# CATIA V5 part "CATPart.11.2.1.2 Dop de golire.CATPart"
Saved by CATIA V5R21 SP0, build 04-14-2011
Part number: Buson de aerisire
Bounding box of the stored display mesh (mm): x 0 to 30, y -13.885 to 13.885, z -13.885 to 13.885
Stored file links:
  C:\Users\MIRCEA\Desktop\MOM\Mogan\model\CATPart.11.2.1.2 Dop de golire.CATPart
  C:\Program Files\Dassault Systemes\B21\win_b64\reffiles\standard\MetricThinPitch.txt
  C:\Program Files\Dassault Systemes\B21\win_b64\reffiles\standard\MetricThickPitch.txt
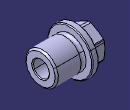
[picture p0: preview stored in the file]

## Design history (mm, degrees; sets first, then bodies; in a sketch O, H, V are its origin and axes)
Parameters
  d = 20 mm
  S = 19 mm
  D = 21.1 mm
  K = 8 mm
  D1 = 28 mm
  b = 18 mm
  l = 30 mm
  d1 = 10 mm
Body1 (main body)
  Sketch1 on xy-plane, origin (0, 0, 0), H (1, 0, 0), V (0, 1, 0)
    line L1 (0, 0) -> (0, 9.5)
    point P1 (0, 9.5)
    line L2 (0, 9.5) -> (0.2813, 10.55)
    line L3 (0.2813, 10.55) -> (8, 10.55)
    line L4 (8, 10.55) -> (8, 14)
    line L5 (8, 14) -> (12, 14)
    line L6 (12, 14) -> (12, 10)
    arc A1 centre (13.5, 10) radius 1.5 from (12, 10) to (15, 10) ccw
    point P8 (15, 10)
    line L7 (15, 10) -> (30, 10)
    line L8 (30, 10) -> (30, 5)
    line L9 (30, 5) -> (8.8868, 5)
    point P12 (6, 0)
    line L10 (6, 0) -> (0, 0)
    line L11 (8.8868, 5) -> (6, 0)
    angle L1 L2 = 15
    distance P1 O = 9.5 {= S/2}
    distance L3 L10 = 10.55 {= D/2}
    distance L9 L10 = 5 {= d1/2}
    distance L10 L5 = 14 {= D1/2}
    distance L7 L10 = 10 {= d/2}
    distance L6 L8 = 18 {= b}
    distance L1 L4 = 8 {= K}
    distance L8 L1 = 30
    distance P12 L8 = 24 {= l-6mm}
    angle L11 L10 = 60
    distance P8 L6 = 3
    distance A1 L10 = 8.5 {= d/2-1.5 mm}
    vertical: L1 V, L4 V, L6 V, L8 V
    horizontal: L3 H, L5 H, L7 H, L9 H, L10 H
    tangency: A1 L6
    coincidence: P12 H
  Shaft1: profile Sketch1, axis Sketch1.H, angle 360
  Sketch2 on face of Shaft1 from Sketch1.L1, origin (0, 0, 0), H (0, -1, 0), V (0, 0, 1)
    point P1 (0.4592, -10.96)
    point P2 (9.7213, -5.0824)
    point P3 (9.2621, 5.8777)
    point P4 (-0.4592, 10.96)
    point P5 (-9.7213, 5.0824)
    point P6 (-9.2621, -5.8777)
    point P7 (5.0902, -8.0212)
    line L1 (0.4592, -10.96) -> (9.7213, -5.0824)
    line L2 (9.7213, -5.0824) -> (9.2621, 5.8777)
    line L3 (9.2621, 5.8777) -> (-0.4592, 10.96)
    line L4 (-0.4592, 10.96) -> (-9.7213, 5.0824)
    line L5 (-9.7213, 5.0824) -> (-9.2621, -5.8777)
    line L6 (-9.2621, -5.8777) -> (0.4592, -10.96)
    construction line L7 (0, 0) -> (5.0902, -8.0212)
    construction circle A1 centre (0, 0) radius 10.9697
    construction arc A2 centre (-9.7213, 5.0824) radius 10.9697 from (-0.4592, 10.96) to (-9.2621, -5.8777) cw
    construction arc A3 centre (9.7213, -5.0824) radius 10.9697 from (9.2621, 5.8777) to (0.4592, -10.96) ccw
    distance L1 L4 = 19 {= S}
    coincidence: A1 P1, A1 P2, A1 P3, A1 P4, A1 P5, A1 P6, A2 O, A3 O
    midpoint: P7 L1
  Pocket1: profile Sketch2, direction (1, 0, 0), length 8 {= K}, outer side
  Fillet1: radius 0.5, on edge [face of Pocket1 | face of Pocket1 from Sketch2.L6]; edge [face of Pocket1 | face of Pocket1 from Sketch2.L1]; edge [face of Pocket1 | face of Pocket1 from Sketch2.L2]; edge [face of Pocket1 | face of Pocket1 from Sketch2.L3]; edge [face of Pocket1 | face of Pocket1 from Sketch2.L4]; edge [face of Pocket1 | face of Pocket1 from Sketch2.L5]
  Chamfer1: length 1, angle 45, on edge [face of Shaft1 from Sketch1.L7 | face of Shaft1 from Sketch1.L8]
  Thread1: "M20x1.5", diameter 20, depth 15 {= b - 3 mm}, pitch 1.5, on face of Shaft1 from Sketch1.L7, from face of Shaft1 from Sketch1.L8
  Chamfer2: length 0.5, angle 45, on edge [face of Shaft1 from Sketch1.L5 | face of Shaft1 from Sketch1.L6]; face of Shaft1 from Sketch1.L5; face of Shaft1 from Sketch1.L9
Relations
  Thread1.Diameter = d (deactivated)
  Thread1.Depth = b - 5 mm (deactivated)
